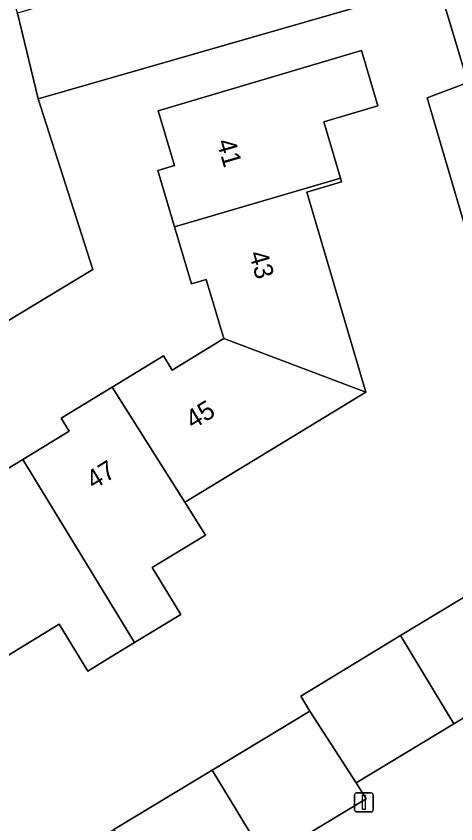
# Model space of a CAD drawing. Extents: x 157767 to 159172, y 387839 to 389425.
# Drawn here: x 158406.39 to 158429.69, y 388404.27 to 388447.09 of the extents above; entities that cross this region are included whole.
import ezdxf

# ---------------------------------------------------------------- set-up
doc = ezdxf.new("R2010")
doc.units = 0
for name, color, linetype in [('IMGEO_Erf', 7, 'Continuous'), ('IMGEO_Lichtmast', 7, 'Continuous'), ('IMGEO_Pand', 7, 'Continuous'), ('IMGEO_Pand_nummerreeks', 7, 'Continuous'), ('IMGEO_Rijbaan_lokaal_open', 7, 'Continuous'), ('IMGEO_Voetpad_open', 7, 'Continuous')]:
    doc.layers.add(name, color=color, linetype=linetype)

msp = doc.modelspace()

# ---------------------------------------------------------------- linework, layer by layer
at = {"layer": 'IMGEO_Erf'}
for points in [[(158428.167, 388442.761), (158430.334, 388443.564), (158428.753, 388448.821), (158407.565, 388442.696), (158410.448, 388433.658), (158402.668, 388428.951), (158372.214, 388410.527)], [(158404.292, 388422.09), (158406.741, 388423.582), (158409.196, 388425.077), (158408.773, 388425.773), (158411.485, 388427.425), (158414.196, 388429.076), (158414.655, 388428.324), (158417.389, 388429.99), (158416.46, 388433.133), (158415.676, 388432.901), (158414.784, 388435.911), (158413.896, 388438.909), (158414.777, 388439.17), (158413.919, 388442.068), (158424.692, 388445.259), (158425.558, 388442.338), (158422.696, 388441.49), (158423.585, 388438.489), (158423.64, 388438.304), (158421.789, 388437.756), (158424.928, 388427.16), (158415.459, 388421.39), (158415.332, 388421.313), (158416.429, 388419.569), (158413.608, 388417.852), (158415.117, 388415.373), (158412.656, 388413.874), (158410.847, 388412.772), (158410.184, 388412.368), (158408.671, 388414.852), (158405.985, 388413.216)], [(158371.074, 388405.904), (158374.439, 388400.385), (158382.856, 388386.58), (158385.462, 388388.157), (158390.713, 388391.335), (158395.905, 388394.476), (158401.118, 388397.631), (158406.388, 388400.82), (158411.577, 388403.96), (158416.775, 388407.106), (158421.953, 388410.239), (158421.469, 388411.04), (158426.763, 388414.244), (158431.966, 388417.393), (158430.624, 388419.611), (158434.316, 388421.846), (158428.167, 388442.761)]]:
    msp.add_lwpolyline(points, dxfattribs=at)
at = {"layer": 'IMGEO_Lichtmast'}
for p, q in [((158424.322, 388405.003), (158424.322, 388405.803)), ((158424.322, 388405.803), (158424.322, 388405.003)), ((158424.422, 388405.903), (158425.212, 388405.903)), ((158425.212, 388405.903), (158424.422, 388405.903)), ((158425.312, 388405.803), (158425.312, 388405.003)), ((158425.312, 388405.003), (158425.312, 388405.803)), ((158425.212, 388404.903), (158424.422, 388404.903)), ((158424.422, 388404.903), (158425.212, 388404.903))]:
    msp.add_line(p, q, dxfattribs=at)
msp.add_lwpolyline([(158424.742, 388405.778), (158424.892, 388405.778), (158424.892, 388405.028), (158424.742, 388405.028), (158424.742, 388405.778)], dxfattribs=at)
for centre, start, end in [((158424.422, 388405.803), 90, 180), ((158424.422, 388405.803), 90, 180), ((158425.212, 388405.803), 0, 90), ((158425.212, 388405.803), 360, 90), ((158424.422, 388405.003), 180, 270), ((158424.422, 388405.003), 180, 270), ((158425.212, 388405.003), 270, 0), ((158425.212, 388405.003), 270, 0)]:
    msp.add_arc(centre, 0.1, start, end, dxfattribs=at)
at = {"layer": 'IMGEO_Pand'}
for points in [[(158433.681, 388444.57), (158439.023, 388446.154), (158437.436, 388451.432), (158434.544, 388450.562), (158428.753, 388448.821), (158430.334, 388443.564)], [(158423.585, 388438.489), (158422.696, 388441.49), (158425.558, 388442.338), (158424.692, 388445.259), (158413.919, 388442.068), (158414.777, 388439.17), (158413.896, 388438.909), (158414.784, 388435.911)], [(158423.585, 388438.489), (158414.784, 388435.911), (158415.676, 388432.901), (158416.46, 388433.133), (158417.389, 388429.99), (158424.928, 388427.16), (158421.789, 388437.756), (158423.64, 388438.304)], [(158424.928, 388427.16), (158417.389, 388429.99), (158414.655, 388428.324), (158414.196, 388429.076), (158411.485, 388427.425), (158415.332, 388421.313), (158415.459, 388421.39)], [(158415.332, 388421.313), (158411.485, 388427.425), (158408.773, 388425.773), (158409.196, 388425.077), (158406.741, 388423.582), (158412.656, 388413.874), (158415.117, 388415.373), (158413.608, 388417.852), (158416.429, 388419.569)], [(158406.741, 388423.582), (158404.292, 388422.09), (158403.888, 388422.753), (158401.119, 388421.067), (158405.985, 388413.216), (158408.671, 388414.852), (158410.184, 388412.368), (158410.847, 388412.772), (158412.656, 388413.874)], [(158426.763, 388414.244), (158429.584, 388409.574), (158434.791, 388412.725), (158431.966, 388417.393)], [(158421.953, 388410.239), (158424.417, 388406.448), (158429.584, 388409.574), (158426.763, 388414.244), (158421.469, 388411.04)], [(158416.775, 388407.106), (158419.647, 388402.39), (158424.936, 388405.591), (158424.417, 388406.448), (158421.953, 388410.239)], [(158414.457, 388399.25), (158419.647, 388402.39), (158416.775, 388407.106), (158411.577, 388403.96)]]:
    msp.add_lwpolyline(points, close=True, dxfattribs=at)
at = {"layer": 'IMGEO_Rijbaan_lokaal_open'}
msp.add_lwpolyline([(158434.544, 388450.562), (158434.092, 388452.282), (158433.309, 388455.261), (158430.867, 388454.531), (158425.589, 388452.954), (158417.027, 388450.396), (158406.469, 388447.241), (158407.565, 388442.696), (158428.753, 388448.821)], close=True, dxfattribs=at)
for points in [[(158430.334, 388443.564), (158428.167, 388442.761), (158434.316, 388421.846)], [(158434.791, 388412.725), (158429.584, 388409.574), (158424.417, 388406.448), (158424.936, 388405.591), (158419.647, 388402.39), (158414.457, 388399.25), (158409.267, 388396.109), (158403.983, 388392.911), (158398.794, 388389.771), (158393.614, 388386.636), (158388.321, 388383.433), (158385.73, 388381.865), (158388.866, 388376.722), (158392.814, 388379.111), (158398.079, 388382.297), (158403.245, 388385.423), (158408.419, 388388.555), (158413.653, 388391.722), (158418.917, 388394.908), (158419.421, 388394.075), (158424.602, 388397.21), (158429.796, 388400.353)]]:
    msp.add_lwpolyline(points, dxfattribs=at)
at = {"layer": 'IMGEO_Voetpad_open'}
msp.add_lwpolyline([(158367.07, 388407.759), (158372.214, 388410.527), (158402.668, 388428.951), (158410.448, 388433.658), (158407.565, 388442.696), (158406.469, 388447.241), (158390.637, 388500), (158386.842, 388512.645), (158385.104, 388518.438)], dxfattribs=at)

# ---------------------------------------------------------------- texts
at = {"layer": 'IMGEO_Pand_nummerreeks'}
for s, rotation, p in [('41', 286.0394, (158417.012, 388440.43)), ('43', 286.0394, (158418.718, 388434.5)), ('45', 31.2663, (158415.756, 388425.16)), ('47', 31.2663, (158410.497, 388421.967))]:
    msp.add_text(s, height=1, rotation=rotation, dxfattribs=at).set_placement(p)

doc.saveas('drawing.dxf')
